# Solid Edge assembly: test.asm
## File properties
Author: Ionut
Template: Iso Assembly.asm
Last saved by: Ionut
Revision: 2
Application: Solid Edge
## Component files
baza.par
glisiera.par
roata.par
bolt_mare.par
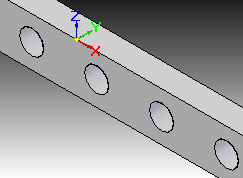
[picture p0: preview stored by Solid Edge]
